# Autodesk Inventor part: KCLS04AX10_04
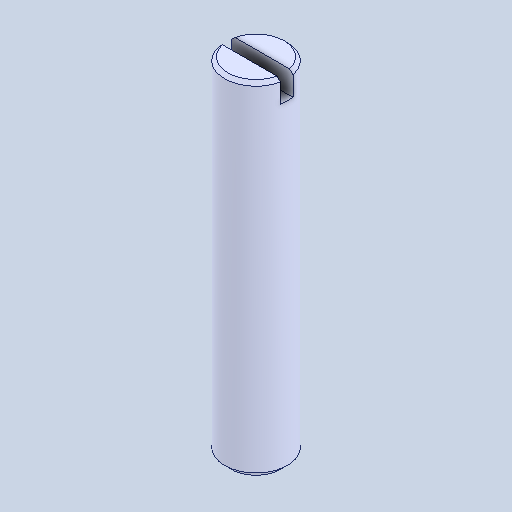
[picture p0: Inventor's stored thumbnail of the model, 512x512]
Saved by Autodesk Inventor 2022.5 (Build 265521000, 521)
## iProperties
Created: 2024-08
Part Number: KCLS04AX10_04
Material: 一般
Document SubType Name: Modeling
Designer: ImaoCorp
Density: 1 g/cm^3
Appearance: 既定
Author: ImaoCorp
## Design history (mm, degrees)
feature "KCLS04AX10_04"
node "ソリッド1"
